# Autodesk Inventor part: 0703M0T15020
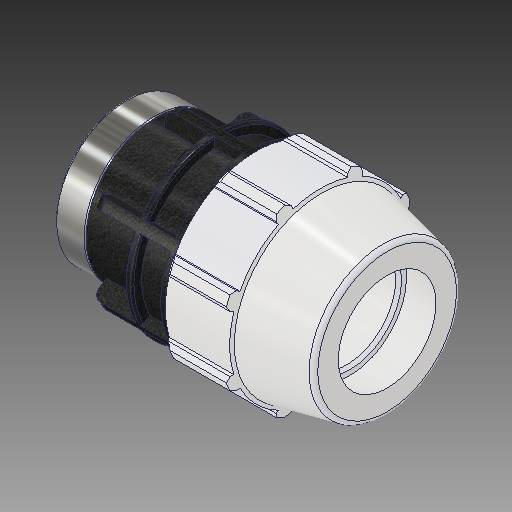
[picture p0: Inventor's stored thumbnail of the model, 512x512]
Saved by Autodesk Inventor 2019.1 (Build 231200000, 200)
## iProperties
Created: 2017-02
Part Number: 0703M0T15020
Material: PVC-Piping
Description: PLASSON FEMALE ADAPTOR G 1 1/2'' - 2''F
Document SubType Name: Modeling
Designer: KIM
Mass: 92.6774 g
Surface Area: 199.44 cm^2
Volume: 66.1981 cm^3
Density: 1.4 g/cm^3
Appearance: PTFE
Author: KIM
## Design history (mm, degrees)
derived "0703M0T.ipt"
feature "Solid1::0703M0T.ipt"
tag "TaggingFeature1"
body "Solid1"
other parameters: "d2" = 48.1, "d4" = 18.43314, "d5" = 32.258, "d7" = 96.012, "d9" = 18.43314, "d11" = 3.68663, "d12" = 76.8096, "d13" = 120 deg, "d14" = 72.15, "d15" = 12 deg, "d16" = 86.4108, "d18" = 2.405, "d19" = 35 deg, "d20" = 17.5 deg, "d21" = 89.29116, "d23" = 0, "d25" = 360 deg, "d27" = 1.92024, "d34" = 4.8006, "d35" = 38.7096, "d36" = 0, "d42" = 32.258, "d43" = 2.88036, "d46" = 1.443, "d49" = 93.98, "d51" = 129.032, "d53" = 0.962, "d55" = 360 deg, "d61" = 29.972, "d62" = 45.695, "d63" = 56.656, "d64" = 43.01067, "d65" = 4.8006, "d66" = 0.5, "d67" = 1, "d68" = 14.986, "d69" = 69.12864, "d70" = 1.27, "d_" = 48.1, "E_" = 96.012, "H_" = 129.032, "l_" = 93.98, "l_2" = 29.972, "G_" = 56.656
